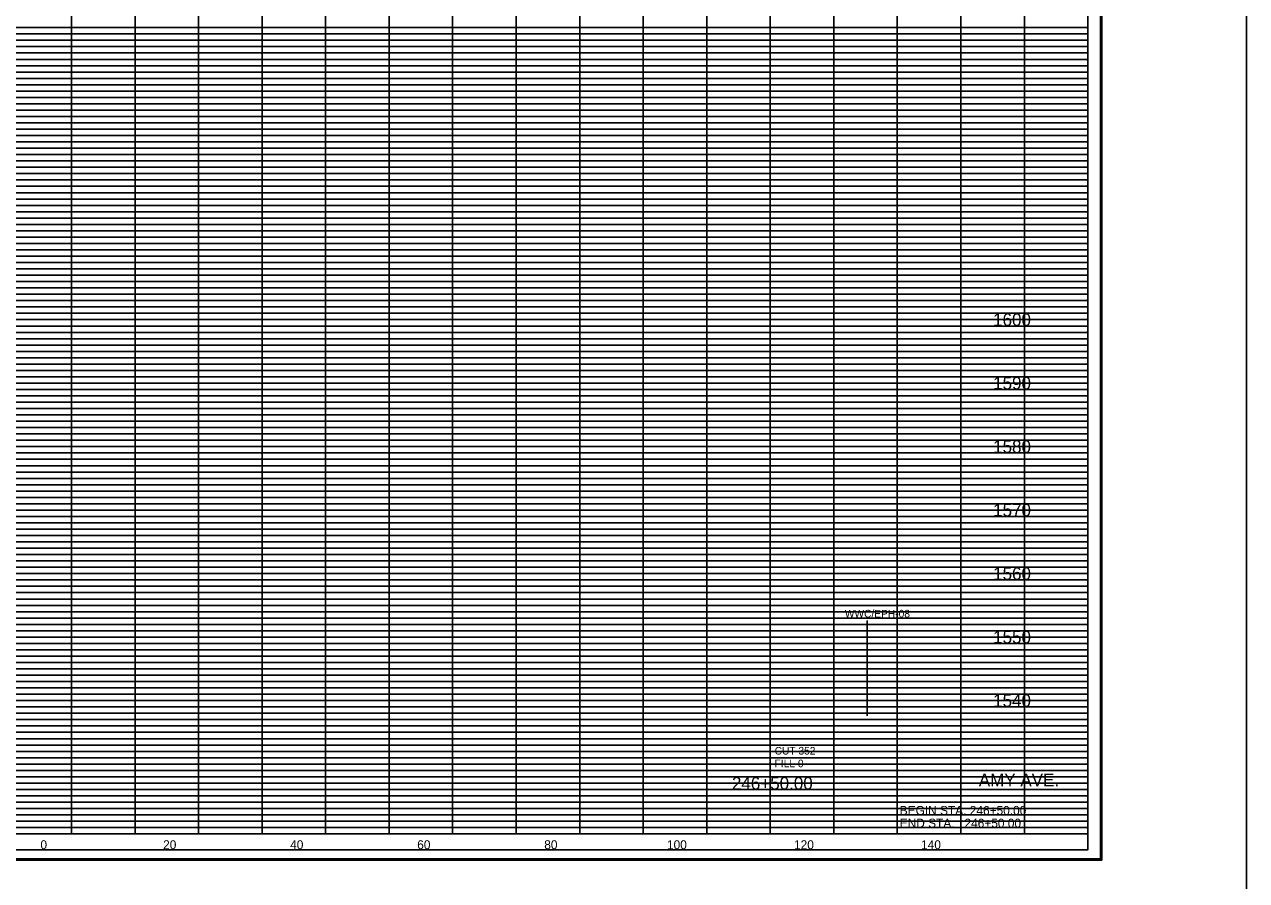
# Model space of a CAD drawing. Extents: x 955 to 1375, y 1248 to 3657.
# Drawn here: x 1152.6 to 1345, y 1802.7 to 1937.5 of the extents above; entities that cross this region are included whole.
import ezdxf

# ---------------------------------------------------------------- set-up
doc = ezdxf.new("R2010")
doc.units = 0
for name, color, linetype in [('DESIGN - SHEET - Corner Text', 7, 'Continuous'), ('DESIGN - SHEET - Light Grid', 7, 'Continuous'), ('DESIGN - SHEET - Linework', 7, 'Continuous'), ('DESIGN - SHEET - Plot Shape', 7, 'Continuous'), ('DESIGN - TYPICAL - Text', 7, 'Continuous'), ('DESIGN - UTILITIES - Cable (Overhead) with Text', 7, 'Continuous'), ('SURVEY - NON-TRANSPORTATION - Features', 7, 'Continuous'), ('SURVEY - NON-TRANSPORTATION - Features Text', 7, 'Continuous')]:
    doc.layers.add(name, color=color, linetype=linetype)

# ---------------------------------------------------------------- blocks, each defined once
blk = doc.blocks.new('XSTSHT')
at = {"layer": 'DESIGN - SHEET - Light Grid'}
for p, q in [((8, 12.7), (16, 12.7)), ((16, 12.7), (24, 12.7)), ((24, 12.7), (32, 12.7)), ((8, 12.6), (16, 12.6)), ((16, 12.6), (24, 12.6)), ((24, 12.6), (32, 12.6)), ((8, 12.5), (16, 12.5)), ((8, 12.4), (16, 12.4)), ((16, 12.5), (24, 12.5)), ((16, 12.4), (24, 12.4)), ((24, 12.5), (32, 12.5)), ((24, 12.4), (32, 12.4)), ((8, 12.3), (16, 12.3)), ((8, 12.2), (16, 12.2)), ((16, 12.3), (24, 12.3)), ((16, 12.2), (24, 12.2)), ((24, 12.3), (32, 12.3)), ((24, 12.2), (32, 12.2)), ((8, 12.1), (16, 12.1)), ((16, 12.1), (24, 12.1)), ((24, 12.1), (32, 12.1)), ((8, 11.9), (16, 11.9)), ((8, 11.8), (16, 11.8)), ((16, 11.9), (24, 11.9)), ((16, 11.8), (24, 11.8)), ((24, 11.9), (32, 11.9)), ((24, 11.8), (32, 11.8)), ((8, 11.7), (16, 11.7)), ((8, 11.6), (16, 11.6)), ((16, 11.7), (24, 11.7)), ((16, 11.6), (24, 11.6)), ((24, 11.7), (32, 11.7)), ((24, 11.6), (32, 11.6)), ((8, 11.5), (16, 11.5)), ((8, 11.4), (16, 11.4)), ((16, 11.5), (24, 11.5)), ((16, 11.4), (24, 11.4)), ((24, 11.5), (32, 11.5)), ((24, 11.4), (32, 11.4)), ((8, 11.3), (16, 11.3)), ((8, 11.2), (16, 11.2)), ((16, 11.3), (24, 11.3)), ((16, 11.2), (24, 11.2)), ((24, 11.3), (32, 11.3)), ((24, 11.2), (32, 11.2)), ((8, 11.1), (16, 11.1)), ((16, 11.1), (24, 11.1)), ((24, 11.1), (32, 11.1)), ((8, 10.9), (16, 10.9)), ((8, 10.8), (16, 10.8)), ((16, 10.9), (24, 10.9)), ((16, 10.8), (24, 10.8)), ((24, 10.9), (32, 10.9)), ((24, 10.8), (32, 10.8)), ((8, 10.7), (16, 10.7)), ((8, 10.6), (16, 10.6)), ((16, 10.7), (24, 10.7)), ((16, 10.6), (24, 10.6)), ((24, 10.7), (32, 10.7)), ((24, 10.6), (32, 10.6)), ((8, 10.5), (16, 10.5)), ((8, 10.4), (16, 10.4)), ((16, 10.5), (24, 10.5)), ((16, 10.4), (24, 10.4)), ((24, 10.5), (32, 10.5)), ((24, 10.4), (32, 10.4)), ((8, 10.3), (16, 10.3)), ((8, 10.2), (16, 10.2)), ((16, 10.3), (24, 10.3)), ((16, 10.2), (24, 10.2)), ((24, 10.3), (32, 10.3)), ((24, 10.2), (32, 10.2)), ((8, 10.1), (16, 10.1)), ((16, 10.1), (24, 10.1)), ((24, 10.1), (32, 10.1)), ((8, 9.9), (16, 9.9)), ((16, 9.9), (24, 9.9)), ((24, 9.9), (32, 9.9)), ((8, 9.8), (16, 9.8)), ((8, 9.7), (16, 9.7)), ((16, 9.8), (24, 9.8)), ((16, 9.7), (24, 9.7)), ((24, 9.8), (32, 9.8)), ((24, 9.7), (32, 9.7)), ((8, 9.6), (16, 9.6)), ((8, 9.5), (16, 9.5)), ((16, 9.6), (24, 9.6)), ((16, 9.5), (24, 9.5)), ((24, 9.6), (32, 9.6)), ((24, 9.5), (32, 9.5)), ((8, 9.4), (16, 9.4)), ((8, 9.3), (16, 9.3)), ((16, 9.4), (24, 9.4)), ((16, 9.3), (24, 9.3)), ((24, 9.4), (32, 9.4)), ((24, 9.3), (32, 9.3)), ((8, 9.2), (16, 9.2)), ((8, 9.1), (16, 9.1)), ((16, 9.2), (24, 9.2)), ((16, 9.1), (24, 9.1)), ((24, 9.2), (32, 9.2)), ((24, 9.1), (32, 9.1)), ((8, 8.9), (16, 8.9)), ((16, 8.9), (24, 8.9)), ((24, 8.9), (32, 8.9)), ((8, 8.8), (16, 8.8)), ((8, 8.7), (16, 8.7)), ((16, 8.8), (24, 8.8)), ((16, 8.7), (24, 8.7)), ((24, 8.8), (32, 8.8)), ((24, 8.7), (32, 8.7)), ((8, 8.6), (16, 8.6)), ((8, 8.5), (16, 8.5)), ((16, 8.6), (24, 8.6)), ((16, 8.5), (24, 8.5)), ((24, 8.6), (32, 8.6)), ((24, 8.5), (32, 8.5)), ((8, 8.4), (16, 8.4)), ((8, 8.3), (16, 8.3)), ((16, 8.4), (24, 8.4)), ((16, 8.3), (24, 8.3)), ((24, 8.4), (32, 8.4)), ((24, 8.3), (32, 8.3)), ((8, 8.2), (16, 8.2)), ((8, 8.1), (16, 8.1)), ((16, 8.2), (24, 8.2)), ((16, 8.1), (24, 8.1)), ((24, 8.2), (32, 8.2)), ((24, 8.1), (32, 8.1)), ((8, 7.9), (16, 7.9)), ((16, 7.9), (24, 7.9)), ((24, 7.9), (32, 7.9)), ((8, 7.8), (16, 7.8)), ((8, 7.7), (16, 7.7)), ((16, 7.8), (24, 7.8)), ((16, 7.7), (24, 7.7)), ((24, 7.8), (32, 7.8)), ((24, 7.7), (32, 7.7)), ((8, 7.6), (16, 7.6)), ((16, 7.6), (24, 7.6)), ((24, 7.6), (32, 7.6)), ((8, 7.5), (16, 7.5)), ((8, 7.4), (16, 7.4)), ((16, 7.5), (24, 7.5)), ((16, 7.4), (24, 7.4)), ((24, 7.5), (32, 7.5)), ((24, 7.4), (32, 7.4)), ((8, 7.3), (16, 7.3)), ((8, 7.2), (16, 7.2)), ((16, 7.3), (24, 7.3)), ((16, 7.2), (24, 7.2)), ((24, 7.3), (32, 7.3)), ((24, 7.2), (32, 7.2)), ((8, 7.1), (16, 7.1)), ((16, 7.1), (24, 7.1)), ((24, 7.1), (32, 7.1)), ((8, 6.9), (16, 6.9)), ((8, 6.8), (16, 6.8)), ((16, 6.9), (24, 6.9)), ((16, 6.8), (24, 6.8)), ((24, 6.9), (32, 6.9)), ((24, 6.8), (32, 6.8)), ((8, 6.7), (16, 6.7)), ((8, 6.6), (16, 6.6)), ((16, 6.7), (24, 6.7)), ((16, 6.6), (24, 6.6)), ((24, 6.7), (32, 6.7)), ((24, 6.6), (32, 6.6)), ((8, 6.5), (16, 6.5)), ((8, 6.4), (16, 6.4)), ((16, 6.5), (24, 6.5)), ((16, 6.4), (24, 6.4)), ((24, 6.5), (32, 6.5)), ((24, 6.4), (32, 6.4)), ((8, 6.3), (16, 6.3)), ((8, 6.2), (16, 6.2)), ((16, 6.3), (24, 6.3)), ((16, 6.2), (24, 6.2)), ((24, 6.3), (32, 6.3)), ((24, 6.2), (32, 6.2)), ((8, 6.1), (16, 6.1)), ((16, 6.1), (24, 6.1)), ((24, 6.1), (32, 6.1)), ((8, 5.9), (16, 5.9)), ((8, 5.8), (16, 5.8)), ((16, 5.9), (24, 5.9)), ((16, 5.8), (24, 5.8)), ((24, 5.9), (32, 5.9)), ((24, 5.8), (32, 5.8)), ((8, 5.7), (16, 5.7)), ((8, 5.6), (16, 5.6)), ((16, 5.7), (24, 5.7)), ((16, 5.6), (24, 5.6)), ((24, 5.7), (32, 5.7)), ((24, 5.6), (32, 5.6)), ((8, 5.5), (16, 5.5)), ((8, 5.4), (16, 5.4)), ((16, 5.5), (24, 5.5)), ((16, 5.4), (24, 5.4)), ((24, 5.5), (32, 5.5)), ((24, 5.4), (32, 5.4)), ((8, 5.3), (16, 5.3)), ((8, 5.2), (16, 5.2)), ((16, 5.3), (24, 5.3)), ((16, 5.2), (24, 5.2)), ((24, 5.3), (32, 5.3)), ((24, 5.2), (32, 5.2)), ((8, 5.1), (16, 5.1)), ((16, 5.1), (24, 5.1)), ((24, 5.1), (32, 5.1)), ((8, 4.9), (16, 4.9)), ((16, 4.9), (24, 4.9)), ((24, 4.9), (32, 4.9)), ((8, 4.8), (16, 4.8)), ((8, 4.7), (16, 4.7)), ((16, 4.8), (24, 4.8)), ((16, 4.7), (24, 4.7)), ((24, 4.8), (32, 4.8)), ((24, 4.7), (32, 4.7)), ((8, 4.6), (16, 4.6)), ((8, 4.5), (16, 4.5)), ((16, 4.6), (24, 4.6)), ((16, 4.5), (24, 4.5)), ((24, 4.6), (32, 4.6)), ((24, 4.5), (32, 4.5)), ((8, 4.4), (16, 4.4)), ((8, 4.3), (16, 4.3)), ((16, 4.4), (24, 4.4)), ((16, 4.3), (24, 4.3)), ((24, 4.4), (32, 4.4)), ((24, 4.3), (32, 4.3)), ((8, 4.2), (16, 4.2)), ((8, 4.1), (16, 4.1)), ((16, 4.2), (24, 4.2)), ((16, 4.1), (24, 4.1)), ((24, 4.2), (32, 4.2)), ((24, 4.1), (32, 4.1)), ((8, 3.9), (16, 3.9)), ((16, 3.9), (24, 3.9)), ((24, 3.9), (32, 3.9)), ((8, 3.8), (16, 3.8)), ((8, 3.7), (16, 3.7)), ((16, 3.8), (24, 3.8)), ((16, 3.7), (24, 3.7)), ((24, 3.8), (32, 3.8)), ((24, 3.7), (32, 3.7)), ((8, 3.6), (16, 3.6)), ((8, 3.5), (16, 3.5)), ((16, 3.6), (24, 3.6)), ((16, 3.5), (24, 3.5)), ((24, 3.6), (32, 3.6)), ((24, 3.5), (32, 3.5)), ((8, 3.4), (16, 3.4)), ((8, 3.3), (16, 3.3)), ((16, 3.4), (24, 3.4)), ((16, 3.3), (24, 3.3)), ((24, 3.4), (32, 3.4)), ((24, 3.3), (32, 3.3)), ((8, 3.2), (16, 3.2)), ((8, 3.1), (16, 3.1)), ((16, 3.2), (24, 3.2)), ((16, 3.1), (24, 3.1)), ((24, 3.2), (32, 3.2)), ((24, 3.1), (32, 3.1)), ((8, 2.9), (16, 2.9)), ((16, 2.9), (24, 2.9)), ((24, 2.9), (32, 2.9)), ((8, 2.8), (16, 2.8)), ((8, 2.7), (16, 2.7)), ((16, 2.8), (24, 2.8)), ((16, 2.7), (24, 2.7)), ((24, 2.8), (32, 2.8)), ((24, 2.7), (32, 2.7)), ((8, 2.6), (16, 2.6)), ((16, 2.6), (24, 2.6)), ((24, 2.6), (32, 2.6)), ((8, 2.5), (16, 2.5)), ((8, 2.4), (16, 2.4)), ((16, 2.5), (24, 2.5)), ((16, 2.4), (24, 2.4)), ((24, 2.5), (32, 2.5)), ((24, 2.4), (32, 2.4)), ((8, 2.3), (16, 2.3)), ((8, 2.2), (16, 2.2)), ((16, 2.3), (24, 2.3)), ((16, 2.2), (24, 2.2)), ((24, 2.3), (32, 2.3)), ((24, 2.2), (32, 2.2)), ((8, 2.1), (16, 2.1)), ((16, 2.1), (24, 2.1)), ((24, 2.1), (32, 2.1)), ((8, 1.9), (16, 1.9)), ((8, 1.8), (16, 1.8)), ((16, 1.9), (24, 1.9)), ((16, 1.8), (24, 1.8)), ((24, 1.9), (32, 1.9)), ((24, 1.8), (32, 1.8)), ((8, 1.7), (16, 1.7)), ((8, 1.6), (16, 1.6)), ((16, 1.7), (24, 1.7)), ((16, 1.6), (24, 1.6)), ((24, 1.7), (32, 1.7)), ((24, 1.6), (32, 1.6)), ((8, 1.5), (16, 1.5)), ((8, 1.4), (16, 1.4)), ((16, 1.5), (24, 1.5)), ((16, 1.4), (24, 1.4)), ((24, 1.5), (32, 1.5)), ((24, 1.4), (32, 1.4)), ((8, 1.3), (16, 1.3)), ((8, 1.2), (16, 1.2)), ((16, 1.3), (24, 1.3)), ((16, 1.2), (24, 1.2)), ((24, 1.3), (32, 1.3)), ((24, 1.2), (32, 1.2)), ((8, 1.1), (16, 1.1)), ((16, 1.1), (24, 1.1)), ((24, 1.1), (32, 1.1)), ((8, 0.9), (16, 0.9)), ((8, 0.8), (16, 0.8)), ((16, 0.9), (24, 0.9)), ((16, 0.8), (24, 0.8)), ((24, 0.9), (32, 0.9)), ((24, 0.8), (32, 0.8)), ((8, 0.7), (16, 0.7)), ((8, 0.6), (16, 0.6)), ((16, 0.7), (24, 0.7)), ((16, 0.6), (24, 0.6)), ((24, 0.7), (32, 0.7)), ((24, 0.6), (32, 0.6)), ((8, 0.5), (16, 0.5)), ((8, 0.4), (16, 0.4)), ((16, 0.5), (24, 0.5)), ((16, 0.4), (24, 0.4)), ((24, 0.5), (32, 0.5)), ((24, 0.4), (32, 0.4)), ((8, 0.3), (16, 0.3)), ((8, 0.2), (16, 0.2)), ((16, 0.3), (24, 0.3)), ((16, 0.2), (24, 0.2)), ((24, 0.3), (32, 0.3)), ((24, 0.2), (32, 0.2)), ((8, 0.1), (16, 0.1)), ((16, 0.1), (24, 0.1)), ((24, 0.1), (32, 0.1))]:
    blk.add_line(p, q, dxfattribs=at)
at = {"layer": 'DESIGN - SHEET - Linework'}
for p, q in [((32.217, 21.414), (32.217, -0.414)), ((16, 0), (16, 21)), ((17, 0), (17, 21)), ((18, 0), (18, 21)), ((19, 0), (19, 21)), ((20, 0), (20, 21)), ((21, 0), (21, 21)), ((22, 0), (22, 21)), ((23, 0), (23, 21)), ((24, 0), (24, 21)), ((25, 0), (25, 21)), ((26, 0), (26, 21)), ((27, 0), (27, 21)), ((28, 0), (28, 20)), ((29, 0), (29, 20)), ((30, 0), (30, 20)), ((31, 0), (31, 20)), ((0, 12), (32, 12)), ((0, 11), (32, 11)), ((0, 10), (32, 10)), ((0, 9), (32, 9)), ((0, 8), (32, 8)), ((0, 7), (32, 7)), ((0, 6), (32, 6)), ((0, 5), (32, 5)), ((0, 4), (32, 4)), ((0, 3), (32, 3)), ((0, 2), (32, 2)), ((0, 1), (32, 1)), ((-1.823, -0.414), (32.217, -0.414))]:
    blk.add_line(p, q, dxfattribs=at)
blk.add_lwpolyline([(0, 21), (0, 0), (32, 0), (32, 21), (0, 21)], dxfattribs=at)
at = {"layer": 'DESIGN - SHEET - Plot Shape'}
for points in [[(-1.803, 21.394), (32.197, 21.394), (32.197, -0.394), (-1.803, -0.394)], [(-0.85, 21), (32, 21), (32, -0.25), (-0.85, -0.25)]]:
    blk.add_lwpolyline(points, close=True, dxfattribs=at)

msp = doc.modelspace()

# ---------------------------------------------------------------- linework, layer by layer
at = {"layer": 'DESIGN - SHEET - Plot Shape'}
msp.add_lwpolyline([(991.5, 1807.5), (1320, 1807.5), (1320, 2020), (991.5, 2020)], close=True, dxfattribs=at)
at = {"layer": 'SURVEY - NON-TRANSPORTATION - Features'}
msp.add_line((1285.27, 1828.62), (1285.27, 1843.62), dxfattribs=at)
at = {"layer": 'SURVEY - NON-TRANSPORTATION - Features Text'}
msp.add_lwpolyline([(955.41, 1505.76), (1344.98, 1505.76), (1344.98, 3398.01), (955.41, 3398.01)], close=True, dxfattribs=at)

# ---------------------------------------------------------------- block references
at = {"layer": 'DESIGN - UTILITIES - Cable (Overhead) with Text', "xscale": 10, "yscale": 10}
msp.add_blockref('XSTSHT', (1000, 1810), dxfattribs=at)

# ---------------------------------------------------------------- texts
at = {"layer": 'DESIGN - SHEET - Corner Text'}
for s, height, p in [('AMY AVE.', 2, (1302.83, 1817.5)), ('BEGIN STA. 246+50.00', 1.4, (1290.38, 1813)), ('END STA.   246+50.00', 1.4, (1290.38, 1811))]:
    msp.add_text(s, height=height, dxfattribs=at).set_placement(p)
at = {"layer": 'DESIGN - TYPICAL - Text'}
for s, height, p in [('     1600     ', 2, (1301.37, 1890)), ('     1590     ', 2, (1301.37, 1880)), ('     1580     ', 2, (1301.37, 1870)), ('     1570     ', 2, (1301.37, 1860)), ('     1560     ', 2, (1301.37, 1850)), ('     1550     ', 2, (1301.37, 1840)), ('     1540     ', 2, (1301.37, 1830)), ('CUT 352', 1.2, (1270.69, 1822.5)), ('FILL 0', 1.2, (1270.69, 1820.5)), ('     246+50.00     ', 2, (1260.25, 1816.97)), ('     0     ', 1.4, (1152.51, 1807.6)), ('     0     ', 1.4, (1152.51, 1807.6)), ('     20     ', 1.4, (1171.82, 1807.6)), ('     40     ', 1.4, (1191.82, 1807.6)), ('     60     ', 1.4, (1211.82, 1807.6)), ('     80     ', 1.4, (1231.82, 1807.6)), ('     100     ', 1.4, (1251.14, 1807.6)), ('     120     ', 1.4, (1271.14, 1807.6)), ('     140     ', 1.4, (1291.14, 1807.6))]:
    msp.add_text(s, height=height, dxfattribs=at).set_placement(p)
at = {"layer": 'SURVEY - NON-TRANSPORTATION - Features'}
msp.add_text('WWC/EPH-08', height=1.2, dxfattribs=at).set_placement((1281.74, 1844.09))

doc.saveas('drawing.dxf')
